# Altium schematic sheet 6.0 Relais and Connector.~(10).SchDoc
size A4; SheetNumber: 6; SheetTotal: 7
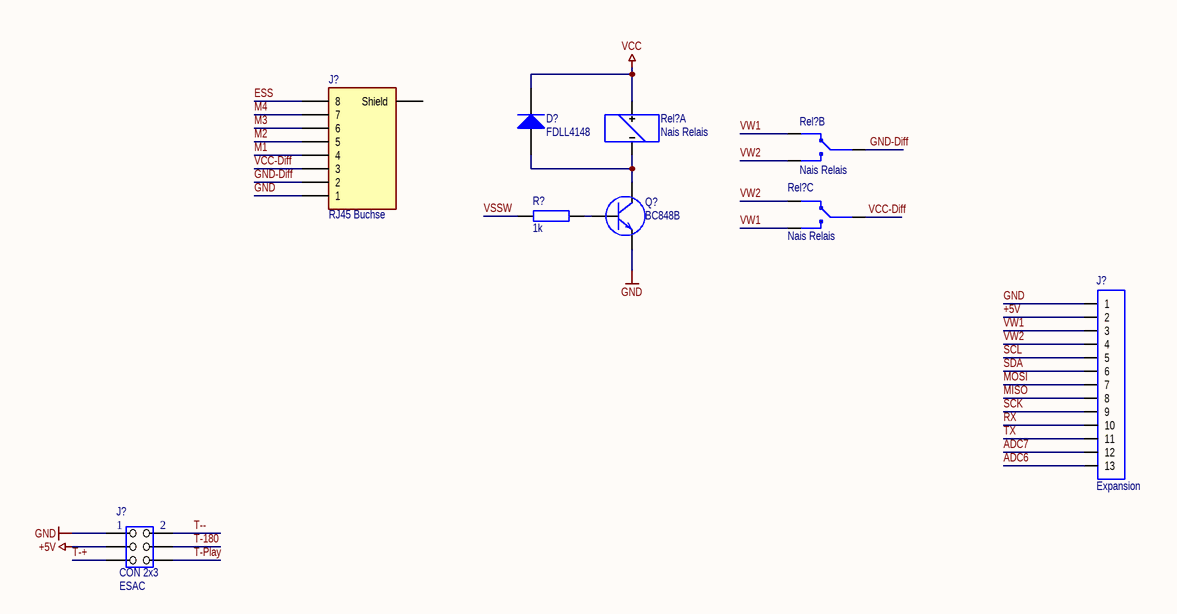
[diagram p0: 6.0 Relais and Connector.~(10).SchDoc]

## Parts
(Parts that share a designator on the sheet are numbered #1, #2 ... from top to bottom, then left to right.)
D?  FDLL4148  [D_SMD_1206]
J?#1  RJ45 Buchse  [J_TE-RJ45-8L-B]
J?#2  Expansion  [SIP-13]
J?#3  CON 2x3  Use: ESAC  [J_2x3]
Q?  BC848B  [SOT-23]
R?  1k  [R_SMD_0805]
Rel?#1  Nais Relais  [Rel_THT_Nais]  (part A of 3)
Rel?#2  Nais Relais  [Rel_THT_Nais]  (part B of 3)
Rel?#3  Nais Relais  [Rel_THT_Nais]  (part C of 3)

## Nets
+5V: J?#2.2 J?#3.3
GND: J?#1.1 J?#2.1 J?#3.1 Q?.2(E)
VCC: D?.2(K) Rel?#1.5
ADC6: J?#2.13
ADC7: J?#2.12
ESS: J?#1.8
GND-Diff: J?#1.2 Rel?#2.3
M1: J?#1.4
M2: J?#1.5
M3: J?#1.6
M4: J?#1.7
MISO: J?#2.8
MOSI: J?#2.7
RX: J?#2.10
SCK: J?#2.9
SCL: J?#2.5
SDA: J?#2.6
T-180: J?#3.4
T-+: J?#3.5
T--: J?#3.2
T-Play: J?#3.6
TX: J?#2.11
VCC-Diff: J?#1.3 Rel?#3.6
VSSW: R?.1
VW1: J?#2.3 Rel?#2.2 Rel?#3.8
VW2: J?#2.4 Rel?#2.1 Rel?#3.7
NetD?_1: D?.1(A) Q?.3(C) Rel?#1.4
NetQ?_1: Q?.1(B) R?.2

Not connected (* = marked no-connect by the designer): J?#1 MP(Shield)

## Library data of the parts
D? = D_SMD_Silizium: Diode SMD Silizium; Spannung For.: 0,7V
J?#1 = J_RJ45: Connector
J?#2 = J_THT_CON13: Stecker
J?#3 = J_THT_IDC 2x3: Stecker
Q? = Q_SMD_NPN: NPN Transistor
R? = R_SMD_Widerstand: Widerstand SMD
Rel?#1-Rel?#3 = Rel_THT_Nais: Nais DS2Y-S-DC12V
